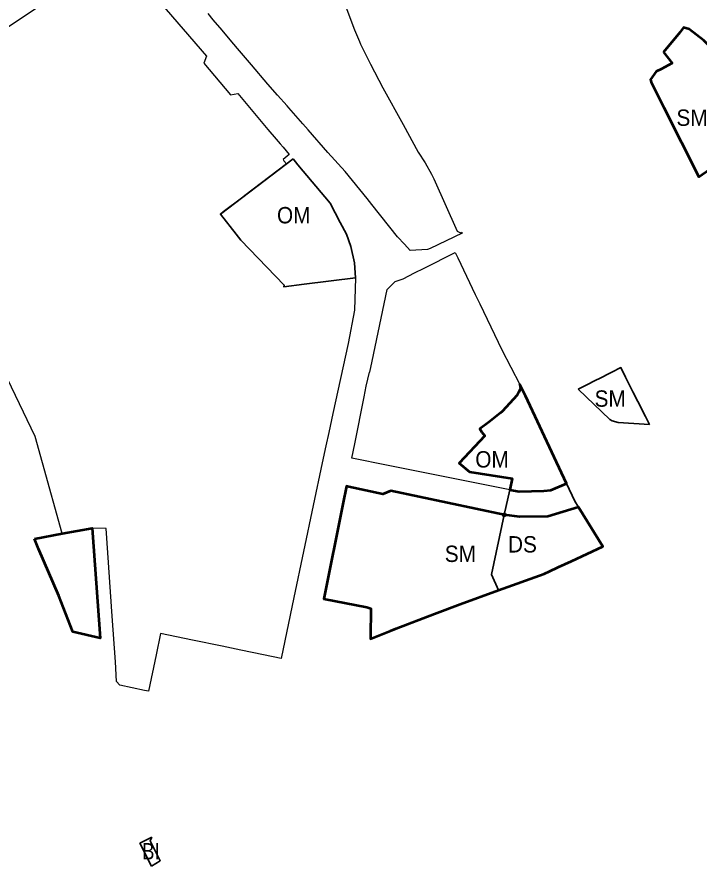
# Model space of a CAD drawing. Extents: x -650276 to -642489, y -1074311 to -1066658.
# Drawn here: x -647429 to -646929, y -1071700 to -1071077 of the extents above; entities that cross this region are included whole.
import ezdxf

# ---------------------------------------------------------------- set-up
doc = ezdxf.new("R2010")
doc.units = 0
doc.header["$LTSCALE"] = 4.8
doc.header["$PDMODE"] = 32
doc.header["$PDSIZE"] = 2.4
for name, color, linetype, lineweight in [('12', 7, 'Continuous', 35), ('15', 7, 'Continuous', 35), ('18', 7, 'Continuous', 35), ('2', 7, 'Continuous', 35), ('24', 7, 'Continuous', 35), ('60', 7, 'Continuous', 53), ('61', 7, 'Continuous', 25)]:
    doc.layers.add(name, color=color, linetype=linetype, lineweight=lineweight)
doc.layers.add('62', color=7, linetype='Continuous')

msp = doc.modelspace()

# ---------------------------------------------------------------- linework, layer by layer
at = {"layer": '12'}
for points in [[(-647226.895, -1071181.511), (-647280.14, -1071221.92), (-647268.52, -1071236.78), (-647265.15, -1071241.1), (-647233.34, -1071274.07), (-647233.64, -1071275.42), (-647218.75, -1071273.32), (-647181.12, -1071268.66), (-647181.99, -1071257.66), (-647184.58, -1071245.67), (-647187.68, -1071236.74), (-647192.29, -1071228.1), (-647199.82, -1071213.98), (-647223.46, -1071185.83)], [(-647056.48, -1071355.32), (-647060.6, -1071346.87), (-647060.22, -1071349.87), (-647061.4, -1071352.51), (-647062.78, -1071354.77), (-647073.68, -1071366.75), (-647075.25, -1071368.01), (-647083.48, -1071374.62), (-647090.04, -1071379.44), (-647088.57, -1071381.97), (-647086.45, -1071384.59), (-647105.2, -1071404.54), (-647097.5, -1071410.96), (-647066.35, -1071415.79), (-647068.162, -1071424.298), (-647061.23, -1071425.434), (-647043.137, -1071424.978), (-647038.119, -1071424.37), (-647026.472, -1071419.614), (-647035.47, -1071400.31)]]:
    msp.add_lwpolyline(points, close=True, dxfattribs=at)
at = {"layer": '15'}
for points in [[(-647072.11, -1071442.6), (-647060.812, -1071444.006), (-647040.089, -1071443.76), (-647017.7, -1071436.79), (-647020.52, -1071432.42), (-647026.472, -1071419.614)], [(-647026.472, -1071419.614), (-647038.119, -1071424.37), (-647043.137, -1071424.978), (-647061.23, -1071425.434), (-647068.162, -1071424.298)], [(-647068.162, -1071424.298), (-647068.162, -1071424.298), (-647072.11, -1071442.6)]]:
    msp.add_lwpolyline(points, dxfattribs=at)
msp.add_point((-647072.11, -1071442.6), dxfattribs=at)
at = {"layer": '18'}
for points in [[(-646955.39, -1071103.23), (-646949.12, -1071111.22), (-646957.26, -1071115.61), (-646960.72, -1071117.25), (-646964.99, -1071123.18), (-646964.43, -1071125.3), (-646955.2, -1071143.67), (-646929.64, -1071194.58), (-646899.85, -1071173.89), (-646881.68, -1071161.83), (-646879.91, -1071161.24), (-646881.97, -1071155.84), (-646887.07, -1071145.66), (-646890.59, -1071140.39), (-646896.62, -1071133.93), (-646904.64, -1071123.54), (-646906.72, -1071120.46), (-646920.54, -1071099.98), (-646925.88, -1071094.68), (-646936.51, -1071086.33), (-646940.67, -1071085.15), (-646943.47, -1071088.69)], [(-647017.93, -1071350.33), (-647013.15, -1071348.01), (-647004.02, -1071343.32), (-647003.37, -1071342.99), (-646993.38, -1071337.85), (-646986.69, -1071334.53), (-646983.33, -1071341.44), (-646977.95, -1071352.38), (-646974.28, -1071359.48), (-646968.63, -1071370.46), (-646965.74, -1071376.18), (-646988.77, -1071374.77), (-646992.95, -1071373.61), (-646994.85, -1071372.49)], [(-647072.11, -1071442.6), (-647155.36, -1071425), (-647161.2, -1071427.33), (-647185.99, -1071421.98), (-647187.85, -1071421.58), (-647190.4, -1071434.75), (-647204.42, -1071504.1), (-647172.74, -1071510.15), (-647170.01, -1071511.22), (-647170.18, -1071532.22), (-647170.23, -1071533.44), (-647155.58, -1071527.62), (-647151.28, -1071525.99), (-647123.17, -1071515.01), (-647104.47, -1071508.08), (-647076.46, -1071497.69), (-647081.488, -1071486.251)]]:
    msp.add_lwpolyline(points, close=True, dxfattribs=at)
at = {"layer": '2'}
for points in [[(-647330.34, -1071678.82), (-647339.211, -1071683.431), (-647330.73, -1071700.09)], [(-647330.73, -1071700.09), (-647324.21, -1071696.2), (-647331.65, -1071681.7), (-647330.34, -1071678.82)]]:
    msp.add_lwpolyline(points, dxfattribs=at)
at = {"layer": '24'}
msp.add_line((-647081.488, -1071486.251), (-647076.46, -1071497.69), dxfattribs=at)
for points in [[(-647017.7, -1071436.79), (-647040.089, -1071443.76), (-647060.812, -1071444.006), (-647072.11, -1071442.6), (-647081.488, -1071486.251)], [(-647076.46, -1071497.69), (-647042.78, -1071485.76), (-647022.81, -1071476.61), (-646999.77, -1071465.81), (-647017.7, -1071436.79)]]:
    msp.add_lwpolyline(points, dxfattribs=at)
at = {"layer": '60'}
for points in [[(-646955.39, -1071103.23), (-646949.12, -1071111.22), (-646957.26, -1071115.61), (-646960.72, -1071117.25), (-646964.99, -1071123.18), (-646964.43, -1071125.3), (-646955.2, -1071143.67), (-646929.64, -1071194.58), (-646899.85, -1071173.89), (-646881.68, -1071161.83), (-646879.91, -1071161.24), (-646881.97, -1071155.84), (-646887.07, -1071145.66), (-646890.59, -1071140.39), (-646896.62, -1071133.93), (-646904.64, -1071123.54), (-646906.72, -1071120.46), (-646920.54, -1071099.98), (-646925.88, -1071094.68), (-646936.51, -1071086.33), (-646940.67, -1071085.15), (-646943.47, -1071088.69)], [(-647056.48, -1071355.32), (-647060.6, -1071346.87), (-647060.22, -1071349.87), (-647061.4, -1071352.51), (-647062.78, -1071354.77), (-647073.68, -1071366.75), (-647075.25, -1071368.01), (-647083.48, -1071374.62), (-647090.04, -1071379.44), (-647088.57, -1071381.97), (-647086.45, -1071384.59), (-647105.2, -1071404.54), (-647097.5, -1071410.96), (-647066.35, -1071415.79), (-647068.162, -1071424.298), (-647061.23, -1071425.434), (-647043.137, -1071424.978), (-647038.119, -1071424.37), (-647026.472, -1071419.614), (-647035.47, -1071400.31)], [(-647072.11, -1071442.6), (-647155.36, -1071425), (-647161.2, -1071427.33), (-647185.99, -1071421.98), (-647187.85, -1071421.58), (-647190.4, -1071434.75), (-647204.42, -1071504.1), (-647172.74, -1071510.15), (-647170.01, -1071511.22), (-647170.18, -1071532.22), (-647170.23, -1071533.44), (-647155.58, -1071527.62), (-647151.28, -1071525.99), (-647123.17, -1071515.01), (-647104.47, -1071508.08), (-647076.46, -1071497.69), (-647042.78, -1071485.76), (-647038.62, -1071483.74), (-647033.09, -1071481.06), (-647032.73, -1071480.88), (-647022.81, -1071476.61), (-646999.77, -1071465.81), (-647017.7, -1071436.79), (-647040.089, -1071443.76), (-647060.812, -1071444.006)], [(-647416.42, -1071460.03), (-647396.02, -1071456.32), (-647374.2, -1071452.36), (-647368.26, -1071532.99), (-647388.29, -1071528.41), (-647398.64, -1071501.96), (-647413.54, -1071467.53)]]:
    msp.add_lwpolyline(points, close=True, dxfattribs=at)
at = {"layer": '61'}
for points in [[(-647442.36, -1071088.82), (-647406.52, -1071065.05)], [(-647324.46, -1071066.41), (-647290.44, -1071106.08), (-647292.31, -1071111.16), (-647272.8, -1071134.42), (-647267.4, -1071133.54), (-647245.43, -1071159.88), (-647239.35, -1071166.98), (-647236.41, -1071170.41), (-647234.12, -1071172.97), (-647229.71, -1071178.23), (-647234.22, -1071182.02), (-647233.57, -1071182.82), (-647231.69, -1071185.15), (-647262.35, -1071208.42), (-647263.8, -1071209.52), (-647278.04, -1071220.33), (-647280.14, -1071221.92), (-647268.52, -1071236.78), (-647265.15, -1071241.1), (-647233.34, -1071274.07), (-647233.64, -1071275.42), (-647209.66, -1071272.22), (-647181.12, -1071268.66), (-647181.79, -1071292.49), (-647186.6, -1071316.98), (-647197.87, -1071368.22), (-647200.76, -1071382.02), (-647202.98, -1071391.98), (-647205.52, -1071404.32), (-647212.07, -1071435.71), (-647226.296, -1071503.249), (-647235.71, -1071547.94), (-647248.51, -1071545.3), (-647265.23, -1071541.68), (-647278.94, -1071538.77), (-647300.51, -1071534.33), (-647324.04, -1071529.54), (-647327.31, -1071545.25), (-647332.86, -1071571.94), (-647335.88, -1071571.31), (-647353.95, -1071567.53), (-647356.2, -1071564.75), (-647357.15, -1071550.44), (-647359.38, -1071516.88), (-647363.86, -1071452.66), (-647374.2, -1071452.36), (-647396.02, -1071456.32), (-647410.56, -1071404.35), (-647415.97, -1071385.01), (-647445, -1071324.99)], [(-647189.68, -1071065.99), (-647181.99, -1071086.74), (-647178.11, -1071095.31), (-647177.46, -1071097.42), (-647170.18, -1071112.08), (-647161.13, -1071129.3), (-647146.28, -1071156.35), (-647135.21, -1071176.44), (-647130.1, -1071184.33), (-647125.44, -1071192.58), (-647123.7, -1071196.19), (-647106.7, -1071234.45), (-647104.17, -1071235.6), (-647103.31, -1071235.22), (-647102.97, -1071235.92), (-647126.477, -1071247.083), (-647128.45, -1071248.02), (-647141.14, -1071248.62), (-647145.16, -1071243.92), (-647150.32, -1071238.51), (-647169.11, -1071214.8), (-647172.63, -1071210.63), (-647188.68, -1071190.78), (-647201.42, -1071176.7), (-647215.86, -1071160.1), (-647219.82, -1071155.78), (-647229.97, -1071144.1), (-647231.32, -1071142.57), (-647238.29, -1071134.66), (-647245.31, -1071126.75), (-647257.41, -1071112.55), (-647267.64, -1071100.44), (-647272.93, -1071094.24), (-647278.77, -1071087.15), (-647285.53, -1071079.39), (-647289.1, -1071074.88)]]:
    msp.add_lwpolyline(points, dxfattribs=at)
msp.add_lwpolyline([(-647093.11, -1071411.77), (-647066.35, -1071415.79), (-647068.162, -1071424.298), (-647097.427, -1071418.318), (-647157.231, -1071406.28), (-647183.816, -1071400.974), (-647181.75, -1071390.51), (-647174.73, -1071356.1), (-647173.24, -1071348.27), (-647170.96, -1071337.84), (-647170.63, -1071337.91), (-647168.91, -1071329.88), (-647157.83, -1071277.35), (-647152.09, -1071271.47), (-647146.3, -1071269.33), (-647137.84, -1071265.06), (-647130.76, -1071261.49), (-647108.16, -1071250.08), (-647106.233, -1071254.01), (-647093.39, -1071280.83), (-647090, -1071287.89), (-647079.25, -1071310.33), (-647073.98, -1071321.53), (-647060.6, -1071346.87), (-647060.22, -1071349.87), (-647061.4, -1071352.51), (-647062.78, -1071354.77), (-647073.68, -1071366.75), (-647075.25, -1071368.01), (-647083.48, -1071374.62), (-647083.48, -1071374.62), (-647090.04, -1071379.44), (-647086.45, -1071384.59), (-647105.2, -1071404.54), (-647097.5, -1071410.96)], close=True, dxfattribs=at)

# ---------------------------------------------------------------- texts
at = {"layer": '62'}
for s, width, p in [('SM', 0.95, (-646945.938, -1071157.245)), ('OM', 0.95, (-647238.703, -1071228.756)), ('SM', 0.95, (-647005.938, -1071363.245)), ('OM', 0.95, (-647093.38, -1071407.817)), ('DS', 0.95, (-647069.386, -1071470.148)), ('SM', 0.95, (-647115.735, -1071477.109)), ('BI', 0.85, (-647337.578, -1071695.247))]:
    msp.add_text(s, height=12, dxfattribs=dict(at, width=width)).set_placement(p)

doc.saveas('drawing.dxf')
